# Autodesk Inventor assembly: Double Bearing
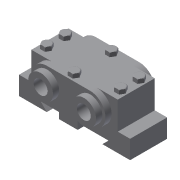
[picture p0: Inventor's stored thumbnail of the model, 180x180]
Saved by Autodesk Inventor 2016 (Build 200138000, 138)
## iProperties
Shininess: 64.0
Length Units: 11269
Angle Units: 11279
Time Units: 11290
Mass Units: 11283
Length Display Precision: 3
Angle Display Precision: 2
Created: 2002-02
Part Number: Double Bearing
Document SubType Name: Assembly
Designer: ***
Density: 0.0
Volumn: 0.0
Area: 0.0
PropertySet Name: Model Information
Control State: 0
Master: False
Checked Out: False
Author: ***
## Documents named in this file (5)
- D:\KAVITA\Autodesk Inventor_ 2016 Project_Kavita\Inventor_Part Files\Inventor_2016_tut\c10_Inv_tut_2016\c10_tut03_inv\Double Bearing Assembly\Double Bearing.iam
- D:\KAVITA\Autodesk Inventor_ 2016 Project_Kavita\Inventor_Part Files\Inventor_2016_tut\c10_Inv_tut_2016\c10_tut03_inv\Double Bearing Assembly\Base.ipt
- D:\KAVITA\Autodesk Inventor_ 2016 Project_Kavita\Inventor_Part Files\Inventor_2016_tut\c10_Inv_tut_2016\c10_tut03_inv\Double Bearing Assembly\Cap.ipt
- D:\KAVITA\Autodesk Inventor_ 2016 Project_Kavita\Inventor_Part Files\Inventor_2016_tut\c10_Inv_tut_2016\c10_tut03_inv\Double Bearing Assembly\Bushing.ipt
- D:\KAVITA\Autodesk Inventor_ 2016 Project_Kavita\Inventor_Part Files\Inventor_2016_tut\c10_Inv_tut_2016\c10_tut03_inv\Double Bearing Assembly\Bolt.ipt
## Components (10 placed, 4 different names)
1. Base:1 — Insert:1, Insert:2
2. Cap:1 — Insert:1, Insert:2, Insert:3, Insert:4, Insert:5, Insert:6
3. Bushing:1 — Insert:3
4. Bushing:2 — Insert:4
5. Bolt:1 — Insert:5
6. Bolt:6
7. Bolt:7
8. Bolt:8
9. Bolt:5 — Insert:6
10. Bolt:9
## Component patterns: Component Pattern 1 (4 elements), Component Pattern 2 (2 elements)
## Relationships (6: Insert 6)
- Insert:1: Base:1 ↔ Cap:1
- Insert:2: Base:1 ↔ Cap:1
- Insert:3: Cap:1 ↔ Bushing:1
- Insert:4: Cap:1 ↔ Bushing:2
- Insert:5: Cap:1 ↔ Bolt:1
- Insert:6: Cap:1 ↔ Bolt:5
